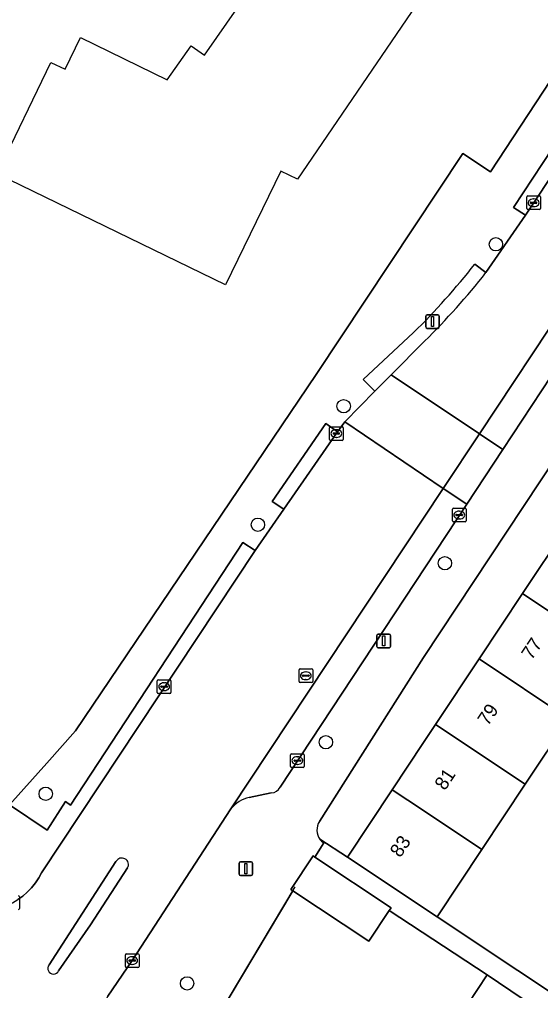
# Model space of a CAD drawing. Extents: x 159279 to 160377, y 384531 to 385888.
# Drawn here: x 159470.4 to 159508.6, y 385153.1 to 385224.2 of the extents above; entities that cross this region are included whole.
import ezdxf

# ---------------------------------------------------------------- set-up
doc = ezdxf.new("R2010")
doc.units = 0
for name, color, linetype in [('IMGEO_Boom', 7, 'Continuous'), ('IMGEO_Erf', 7, 'Continuous'), ('IMGEO_Groenvoorziening', 7, 'Continuous'), ('IMGEO_Hek', 7, 'Continuous'), ('IMGEO_Kolk', 7, 'Continuous'), ('IMGEO_Lichtmast', 7, 'Continuous'), ('IMGEO_Muur', 7, 'Continuous'), ('IMGEO_Pand', 7, 'Continuous'), ('IMGEO_Pand_nummerreeks', 7, 'Continuous'), ('IMGEO_Pand_vergunning_verleend', 7, 'Continuous'), ('IMGEO_Parkeervlak_open', 7, 'Continuous'), ('IMGEO_Rijbaan_lokaal_open', 7, 'Continuous'), ('IMGEO_Rioolput', 7, 'Continuous'), ('IMGEO_Verkeerseiland_gesloten', 7, 'Continuous'), ('IMGEO_Voetpad_open', 7, 'Continuous')]:
    doc.layers.add(name, color=color, linetype=linetype)

msp = doc.modelspace()

# ---------------------------------------------------------------- linework, layer by layer
at = {"layer": 'IMGEO_Boom'}
for centre in [(159505.303, 385207.734), (159494.152, 385195.876), (159487.871, 385187.199), (159501.57, 385184.377), (159492.848, 385171.268), (159472.328, 385167.492), (159482.683, 385153.611)]:
    msp.add_circle(centre, 0.489, dxfattribs=at)
at = {"layer": 'IMGEO_Erf'}
for points in [[(159530.535, 385223.584), (159500, 385177.475), (159492.38, 385165.468)], [(159492.402, 385164.162), (159494.421, 385162.858), (159497.704, 385167.792), (159500, 385171.242), (159500.889, 385172.578), (159504.075, 385177.365), (159507.261, 385182.153), (159510.446, 385186.939)], [(159510.641, 385172.99), (159507.456, 385168.204), (159504.27, 385163.417), (159500.989, 385158.486), (159512.815, 385150.618)], [(159518.635, 385141.802), (159516.069, 385143.517), (159513.503, 385145.232), (159510.937, 385146.948), (159508.371, 385148.663), (159505.805, 385150.378), (159503.239, 385152.093), (159504.664, 385154.224), (159497.479, 385158.937), (159495.985, 385156.692), (159490.429, 385160.388), (159484.85, 385151.066)]]:
    msp.add_lwpolyline(points, dxfattribs=at)
msp.add_arc((159493.374, 385164.832), 1.18, 147.37085, 214.5593, dxfattribs=at)
at = {"layer": 'IMGEO_Groenvoorziening'}
for points in [[(159546.86, 385274.842), (159546.212, 385275.888), (159529.172, 385250), (159504.899, 385213.047), (159502.888, 385214.394), (159492.142, 385198.211), (159474.504, 385172.106), (159472.407, 385169.747), (159469.674, 385166.696), (159472.443, 385164.841), (159473.77, 385166.921), (159474.152, 385166.668), (159486.771, 385185.901), (159487.681, 385185.313), (159489.779, 385188.336), (159488.914, 385188.908), (159492.841, 385194.619), (159493.711, 385194.005), (159494.162, 385194.645), (159494.243, 385194.728), (159496.427, 385196.975), (159495.586, 385197.832), (159499.271, 385201.267)], [(159503.765, 385206.282), (159504.576, 385205.661), (159507.461, 385209.864), (159506.582, 385210.436), (159511.549, 385217.953), (159512.448, 385217.36), (159515.225, 385221.522), (159514.344, 385222.135), (159519.542, 385230.066), (159520.431, 385229.512), (159522.635, 385232.842), (159521.758, 385233.406), (159534.923, 385253.438)], [(159436.757, 385236.409), (159430.587, 385217.007), (159435.719, 385206.014), (159438.506, 385200.578), (159441.573, 385195.295), (159443.21, 385192.716), (159445.93, 385188.732), (159465.252, 385165.282), (159467.724, 385165.189), (159469.674, 385166.696), (159472.407, 385169.747), (159474.504, 385172.106), (159492.142, 385198.211), (159502.888, 385214.394), (159504.899, 385213.047), (159529.172, 385250)]]:
    msp.add_lwpolyline(points, dxfattribs=at)
msp.add_arc((159460.86, 385240.209), 54.698, 314.60702, 321.6652, dxfattribs=at)
at = {"layer": 'IMGEO_Hek'}
msp.add_lwpolyline([(159529.172, 385250), (159504.899, 385213.047), (159502.888, 385214.394), (159492.142, 385198.211), (159474.504, 385172.106), (159472.407, 385169.747), (159469.674, 385166.696)], dxfattribs=at)
at = {"layer": 'IMGEO_Kolk'}
for p, q in [((159507.566, 385210.348), (159507.566, 385211.2)), ((159507.641, 385211.274), (159508.493, 385211.274)), ((159507.825, 385210.768), (159507.825, 385210.78)), ((159507.868, 385210.817), (159508.266, 385210.817)), ((159508.054, 385211.054), (159508.079, 385211.054)), ((159508.309, 385210.78), (159508.309, 385210.768)), ((159508.567, 385211.2), (159508.567, 385210.348)), ((159508.493, 385210.274), (159507.641, 385210.274)), ((159508.263, 385210.731), (159507.865, 385210.731)), ((159508.077, 385210.494), (159508.052, 385210.494)), ((159493.114, 385193.451), (159493.114, 385194.303)), ((159493.189, 385194.377), (159494.041, 385194.377)), ((159493.373, 385193.871), (159493.373, 385193.883)), ((159493.811, 385193.834), (159493.413, 385193.834)), ((159493.416, 385193.92), (159493.814, 385193.92)), ((159493.602, 385194.157), (159493.627, 385194.157)), ((159493.857, 385193.883), (159493.857, 385193.871)), ((159494.115, 385194.303), (159494.115, 385193.451)), ((159494.041, 385193.377), (159493.189, 385193.377)), ((159493.625, 385193.597), (159493.6, 385193.597)), ((159502.12, 385187.483), (159502.12, 385188.335)), ((159502.195, 385188.409), (159503.047, 385188.409)), ((159502.608, 385188.189), (159502.633, 385188.189)), ((159503.121, 385188.335), (159503.121, 385187.483)), ((159503.047, 385187.409), (159502.195, 385187.409)), ((159502.379, 385187.903), (159502.379, 385187.915)), ((159502.817, 385187.866), (159502.419, 385187.866)), ((159502.422, 385187.952), (159502.82, 385187.952)), ((159502.631, 385187.629), (159502.606, 385187.629)), ((159502.863, 385187.915), (159502.863, 385187.903)), ((159480.503, 385174.912), (159480.503, 385175.764)), ((159480.578, 385175.838), (159481.43, 385175.838)), ((159480.762, 385175.332), (159480.762, 385175.344)), ((159481.2, 385175.295), (159480.802, 385175.295)), ((159480.805, 385175.381), (159481.203, 385175.381)), ((159480.991, 385175.618), (159481.016, 385175.618)), ((159481.246, 385175.344), (159481.246, 385175.332)), ((159481.504, 385175.764), (159481.504, 385174.912)), ((159481.43, 385174.838), (159480.578, 385174.838)), ((159481.014, 385175.058), (159480.989, 385175.058)), ((159490.26, 385169.496), (159490.26, 385170.348)), ((159490.335, 385170.422), (159491.187, 385170.422)), ((159491.261, 385170.348), (159491.261, 385169.496)), ((159490.519, 385169.916), (159490.519, 385169.928)), ((159490.957, 385169.879), (159490.559, 385169.879)), ((159490.562, 385169.965), (159490.96, 385169.965)), ((159490.771, 385169.642), (159490.746, 385169.642)), ((159490.748, 385170.202), (159490.773, 385170.202)), ((159491.003, 385169.928), (159491.003, 385169.916)), ((159491.187, 385169.422), (159490.335, 385169.422)), ((159470.401, 385159.939), (159470.401, 385159.087)), ((159478.16, 385154.855), (159478.16, 385155.707)), ((159478.235, 385155.781), (159479.087, 385155.781)), ((159478.419, 385155.275), (159478.419, 385155.287)), ((159478.462, 385155.324), (159478.86, 385155.324)), ((159478.648, 385155.561), (159478.673, 385155.561)), ((159478.903, 385155.287), (159478.903, 385155.275)), ((159479.161, 385155.707), (159479.161, 385154.855)), ((159479.087, 385154.781), (159478.235, 385154.781)), ((159478.857, 385155.238), (159478.459, 385155.238)), ((159478.671, 385155.001), (159478.646, 385155.001))]:
    msp.add_line(p, q, dxfattribs=at)
for points in [[(159507.566, 385210.348), (159507.566, 385211.2)], [(159507.641, 385211.274), (159508.493, 385211.274)], [(159508.567, 385211.2), (159508.567, 385210.348)], [(159508.493, 385210.274), (159507.641, 385210.274)], [(159493.114, 385193.451), (159493.114, 385194.303)], [(159493.189, 385194.377), (159494.041, 385194.377)], [(159494.115, 385194.303), (159494.115, 385193.451)], [(159494.041, 385193.377), (159493.189, 385193.377)], [(159502.12, 385187.483), (159502.12, 385188.335)], [(159502.195, 385188.409), (159503.047, 385188.409)], [(159503.121, 385188.335), (159503.121, 385187.483)], [(159503.047, 385187.409), (159502.195, 385187.409)], [(159480.503, 385174.912), (159480.503, 385175.764)], [(159480.578, 385175.838), (159481.43, 385175.838)], [(159481.504, 385175.764), (159481.504, 385174.912)], [(159481.43, 385174.838), (159480.578, 385174.838)], [(159490.26, 385169.496), (159490.26, 385170.348)], [(159490.335, 385170.422), (159491.187, 385170.422)], [(159491.261, 385170.348), (159491.261, 385169.496)], [(159491.187, 385169.422), (159490.335, 385169.422)], [(159470.401, 385159.939), (159470.401, 385159.087)], [(159478.16, 385154.855), (159478.16, 385155.707)], [(159478.235, 385155.781), (159479.087, 385155.781)], [(159479.161, 385155.707), (159479.161, 385154.855)], [(159479.087, 385154.781), (159478.235, 385154.781)]]:
    msp.add_lwpolyline(points, dxfattribs=at)
for centre, radius, start, end in [((159507.643, 385211.198), 0.0765, 91.55205, 178.44795), ((159507.643, 385211.198), 0.0765, 91.55205, 178.44795), ((159507.865, 385210.777), 0.0403, 85.87752, 175.75265), ((159507.862, 385210.767), 0.0366, 178.93798, 274.71019), ((159508.266, 385210.774), 0.043, 264.86636, 352.45326), ((159508.27, 385210.779), 0.0386, 1.73085, 96.63898), ((159508.491, 385211.198), 0.0765, 1.55205, 88.44795), ((159508.491, 385211.198), 0.0765, 1.55205, 88.44795), ((159507.643, 385210.35), 0.0765, 181.55205, 268.44795), ((159507.643, 385210.35), 0.0765, 181.55205, 268.44795), ((159508.491, 385210.35), 0.0765, 271.55205, 358.44795), ((159508.491, 385210.35), 0.0765, 271.55205, 358.44795), ((159493.191, 385194.301), 0.0765, 91.55205, 178.44795), ((159493.191, 385194.301), 0.0765, 91.55205, 178.44795), ((159493.413, 385193.88), 0.0403, 85.87752, 175.75265), ((159493.41, 385193.87), 0.0366, 178.93798, 274.71019), ((159493.814, 385193.877), 0.043, 264.86636, 352.45326), ((159493.818, 385193.882), 0.0386, 1.73085, 96.63898), ((159494.039, 385194.301), 0.0765, 1.55205, 88.44795), ((159494.039, 385194.301), 0.0765, 1.55205, 88.44795), ((159493.191, 385193.453), 0.0765, 181.55205, 268.44795), ((159493.191, 385193.453), 0.0765, 181.55205, 268.44795), ((159494.039, 385193.453), 0.0765, 271.55205, 358.44795), ((159494.039, 385193.453), 0.0765, 271.55205, 358.44795), ((159502.197, 385188.333), 0.0765, 91.55205, 178.44795), ((159502.197, 385188.333), 0.0765, 91.55205, 178.44795), ((159503.045, 385188.333), 0.0765, 1.55205, 88.44795), ((159503.045, 385188.333), 0.0765, 1.55205, 88.44795), ((159502.197, 385187.485), 0.0765, 181.55205, 268.44795), ((159502.197, 385187.485), 0.0765, 181.55205, 268.44795), ((159502.419, 385187.912), 0.0403, 85.87752, 175.75265), ((159502.416, 385187.902), 0.0366, 178.93798, 274.71019), ((159502.82, 385187.909), 0.043, 264.86636, 352.45326), ((159502.824, 385187.914), 0.0386, 1.73085, 96.63898), ((159503.045, 385187.485), 0.0765, 271.55205, 358.44795), ((159503.045, 385187.485), 0.0765, 271.55205, 358.44795), ((159480.58, 385175.762), 0.0765, 91.55205, 178.44795), ((159480.58, 385175.762), 0.0765, 91.55205, 178.44795), ((159480.802, 385175.341), 0.0403, 85.87752, 175.75265), ((159480.799, 385175.331), 0.0366, 178.93798, 274.71019), ((159481.203, 385175.338), 0.043, 264.86636, 352.45326), ((159481.207, 385175.343), 0.0386, 1.73085, 96.63898), ((159481.428, 385175.762), 0.0765, 1.55205, 88.44795), ((159481.428, 385175.762), 0.0765, 1.55205, 88.44795), ((159480.58, 385174.914), 0.0765, 181.55205, 268.44795), ((159480.58, 385174.914), 0.0765, 181.55205, 268.44795), ((159481.428, 385174.914), 0.0765, 271.55205, 358.44795), ((159481.428, 385174.914), 0.0765, 271.55205, 358.44795), ((159490.337, 385170.346), 0.0765, 91.55205, 178.44795), ((159490.337, 385170.346), 0.0765, 91.55205, 178.44795), ((159491.185, 385170.346), 0.0765, 1.55205, 88.44795), ((159491.185, 385170.346), 0.0765, 1.55205, 88.44795), ((159490.559, 385169.925), 0.0403, 85.87752, 175.75265), ((159490.556, 385169.915), 0.0366, 178.93798, 274.71019), ((159490.96, 385169.922), 0.043, 264.86636, 352.45326), ((159490.964, 385169.927), 0.0386, 1.73085, 96.63898), ((159490.337, 385169.498), 0.0765, 181.55205, 268.44795), ((159490.337, 385169.498), 0.0765, 181.55205, 268.44795), ((159491.185, 385169.498), 0.0765, 271.55205, 358.44795), ((159491.185, 385169.498), 0.0765, 271.55205, 358.44795), ((159470.325, 385159.937), 0.0765, 1.55205, 88.44795), ((159470.325, 385159.937), 0.0765, 1.55205, 88.44795), ((159470.325, 385159.089), 0.0765, 271.55205, 358.44795), ((159470.325, 385159.089), 0.0765, 271.55205, 358.44795), ((159478.237, 385155.705), 0.0765, 91.55205, 178.44795), ((159478.237, 385155.705), 0.0765, 91.55205, 178.44795), ((159478.459, 385155.284), 0.0403, 85.87752, 175.75265), ((159478.864, 385155.286), 0.0386, 1.73085, 96.63898), ((159479.085, 385155.705), 0.0765, 1.55205, 88.44795), ((159479.085, 385155.705), 0.0765, 1.55205, 88.44795), ((159478.237, 385154.857), 0.0765, 181.55205, 268.44795), ((159478.237, 385154.857), 0.0765, 181.55205, 268.44795), ((159478.456, 385155.274), 0.0366, 178.93798, 274.71019), ((159478.86, 385155.281), 0.043, 264.86636, 352.45326), ((159479.085, 385154.857), 0.0765, 271.55205, 358.44795), ((159479.085, 385154.857), 0.0765, 271.55205, 358.44795)]:
    msp.add_arc(centre, radius, start, end, dxfattribs=at)
for centre, major_axis, ratio, start_param, end_param in [((159508.053, 385210.774), (-0.387, 0.002), 0.722429, 4.712389, 7.853982), ((159508.078, 385210.774), (-0.39, 0.002), 0.717154, 1.570796, 4.712389), ((159493.601, 385193.877), (-0.387, 0.002), 0.722429, 4.712389, 7.853982), ((159493.626, 385193.877), (-0.39, 0.002), 0.717154, 1.570796, 4.712389), ((159502.607, 385187.909), (-0.387, 0.002), 0.722429, 4.712389, 7.853982), ((159502.632, 385187.909), (-0.39, 0.002), 0.717154, 1.570796, 4.712389), ((159480.99, 385175.338), (-0.387, 0.002), 0.722429, 4.712389, 7.853982), ((159481.015, 385175.338), (-0.39, 0.002), 0.717154, 1.570796, 4.712389), ((159490.747, 385169.922), (-0.387, 0.002), 0.722429, 4.712389, 7.853982), ((159490.772, 385169.922), (-0.39, 0.002), 0.717154, 1.570796, 4.712389), ((159478.647, 385155.281), (-0.387, 0.002), 0.722429, 4.712389, 7.853982), ((159478.672, 385155.281), (-0.39, 0.002), 0.717154, 1.570796, 4.712389)]:
    msp.add_ellipse(centre, major_axis=major_axis, ratio=ratio, start_param=start_param, end_param=end_param, dxfattribs=at)
at = {"layer": 'IMGEO_Lichtmast'}
for p, q in [((159500.162, 385201.68), (159500.162, 385202.48)), ((159500.162, 385202.48), (159500.162, 385201.68)), ((159500.262, 385202.58), (159501.052, 385202.58)), ((159501.052, 385202.58), (159500.262, 385202.58)), ((159501.152, 385202.48), (159501.152, 385201.68)), ((159501.152, 385201.68), (159501.152, 385202.48)), ((159501.052, 385201.58), (159500.262, 385201.58)), ((159500.262, 385201.58), (159501.052, 385201.58)), ((159496.586, 385178.292), (159496.586, 385179.092)), ((159496.586, 385179.092), (159496.586, 385178.292)), ((159496.686, 385179.192), (159497.476, 385179.192)), ((159497.476, 385179.192), (159496.686, 385179.192)), ((159497.576, 385179.092), (159497.576, 385178.292)), ((159497.576, 385178.292), (159497.576, 385179.092)), ((159497.476, 385178.192), (159496.686, 385178.192)), ((159496.686, 385178.192), (159497.476, 385178.192)), ((159486.486, 385161.614), (159486.486, 385162.414)), ((159486.486, 385162.414), (159486.486, 385161.614)), ((159486.586, 385162.514), (159487.376, 385162.514)), ((159487.376, 385162.514), (159486.586, 385162.514)), ((159487.476, 385162.414), (159487.476, 385161.614)), ((159487.476, 385161.614), (159487.476, 385162.414)), ((159487.376, 385161.514), (159486.586, 385161.514)), ((159486.586, 385161.514), (159487.376, 385161.514))]:
    msp.add_line(p, q, dxfattribs=at)
for points in [[(159500.582, 385202.455), (159500.732, 385202.455), (159500.732, 385201.705), (159500.582, 385201.705), (159500.582, 385202.455)], [(159497.006, 385179.067), (159497.156, 385179.067), (159497.156, 385178.317), (159497.006, 385178.317), (159497.006, 385179.067)], [(159486.906, 385162.389), (159487.056, 385162.389), (159487.056, 385161.639), (159486.906, 385161.639), (159486.906, 385162.389)]]:
    msp.add_lwpolyline(points, dxfattribs=at)
for centre, start, end in [((159500.262, 385202.48), 90, 180), ((159500.262, 385202.48), 90, 180), ((159501.052, 385202.48), 0, 90), ((159501.052, 385202.48), 360, 90), ((159500.262, 385201.68), 180, 270), ((159500.262, 385201.68), 180, 270), ((159501.052, 385201.68), 270, 0), ((159501.052, 385201.68), 270, 0), ((159496.686, 385179.092), 90, 180), ((159496.686, 385179.092), 90, 180), ((159497.476, 385179.092), 0, 90), ((159497.476, 385179.092), 360, 90), ((159496.686, 385178.292), 180, 270), ((159496.686, 385178.292), 180, 270), ((159497.476, 385178.292), 270, 0), ((159497.476, 385178.292), 270, 0), ((159486.586, 385162.414), 90, 180), ((159486.586, 385162.414), 90, 180), ((159487.376, 385162.414), 0, 90), ((159487.376, 385162.414), 360, 90), ((159486.586, 385161.614), 180, 270), ((159486.586, 385161.614), 180, 270), ((159487.376, 385161.614), 270, 0), ((159487.376, 385161.614), 270, 0)]:
    msp.add_arc(centre, 0.1, start, end, dxfattribs=at)
at = {"layer": 'IMGEO_Muur'}
msp.add_lwpolyline([(159484.85, 385151.066), (159490.607, 385160.686)], dxfattribs=at)
at = {"layer": 'IMGEO_Pand'}
for points in [[(159517.013, 385182.564), (159510.446, 385186.939), (159507.261, 385182.153), (159513.827, 385177.778)], [(159513.827, 385177.778), (159507.261, 385182.153), (159504.075, 385177.365), (159510.641, 385172.99)], [(159510.641, 385172.99), (159504.075, 385177.365), (159500.889, 385172.578), (159507.456, 385168.204)], [(159507.456, 385168.204), (159500.889, 385172.578), (159500, 385171.242), (159497.704, 385167.792), (159500, 385166.262), (159504.27, 385163.417)], [(159500, 385159.144), (159500.989, 385158.486), (159504.27, 385163.417), (159500, 385166.262), (159497.704, 385167.792), (159494.421, 385162.858), (159498.583, 385160.087)], [(159492.047, 385162.863), (159491.928, 385162.942), (159490.291, 385160.48), (159490.429, 385160.388), (159495.985, 385156.692), (159497.479, 385158.937), (159497.623, 385159.154)], [(159503.239, 385152.093), (159505.805, 385150.378), (159507.23, 385152.509), (159504.664, 385154.224)]]:
    msp.add_lwpolyline(points, close=True, dxfattribs=at)
at = {"layer": 'IMGEO_Pand_vergunning_verleend'}
msp.add_lwpolyline([(159468.752, 385212.898), (159472.711, 385221.059), (159473.742, 385220.559), (159474.865, 385222.874), (159481.236, 385219.784), (159482.972, 385222.272), (159483.963, 385221.581), (159499.764, 385244.237), (159508.203, 385238.094), (159490.769, 385212.5), (159489.54, 385213.096), (159485.502, 385204.772)], close=True, dxfattribs=at)
at = {"layer": 'IMGEO_Parkeervlak_open'}
for points in [[(159523.226, 385222.717), (159504.103, 385193.86), (159505.818, 385192.716), (159513.601, 385204.527)], [(159489.511, 385167.971), (159503.167, 385188.694), (159501.449, 385189.855), (159485.898, 385166.387)], [(159487.223, 385167.226), (159488.849, 385167.561)]]:
    msp.add_lwpolyline(points, dxfattribs=at)
msp.add_lwpolyline([(159504.103, 385193.86), (159501.449, 385189.855), (159503.167, 385188.694), (159505.818, 385192.716)], close=True, dxfattribs=at)
for centre, radius, start, end in [((159488.812, 385168.361), 0.801, 272.68057, 330.86222), ((159487.759, 385164.914), 2.373, 103.04715, 141.63745)]:
    msp.add_arc(centre, radius, start, end, dxfattribs=at)
at = {"layer": 'IMGEO_Rijbaan_lokaal_open'}
for points in [[(159553.737, 385268.934), (159548.67, 385272.278), (159546.87, 385269.625), (159546.274, 385268.656), (159544.102, 385265.394), (159538.681, 385256.977), (159535.917, 385252.765), (159522.635, 385232.842), (159520.431, 385229.512), (159515.225, 385221.522), (159512.448, 385217.36), (159507.461, 385209.864), (159504.576, 385205.661)], [(159500.082, 385200.646), (159497.627, 385198.181), (159504.103, 385193.86), (159523.226, 385222.717), (159525.008, 385225.421), (159526.049, 385227.003), (159533.84, 385238.844), (159537.02, 385243.683), (159537.125, 385243.823), (159537.243, 385243.954), (159537.371, 385244.074), (159553.737, 385268.934)], [(159476.871, 385152.664), (159478.661, 385155.281), (159485.898, 385166.387), (159501.449, 385189.855), (159494.243, 385194.728), (159494.162, 385194.645), (159493.711, 385194.005), (159489.779, 385188.336), (159487.681, 385185.313), (159472.022, 385161.709), (159471.816, 385161.332), (159471.569, 385160.961), (159471.29, 385160.614), (159470.981, 385160.293), (159470.645, 385160.001), (159470.284, 385159.74)], [(159472.573, 385154.961), (159477.473, 385162.537)], [(159478.328, 385162.066), (159475.601, 385157.886), (159473.273, 385154.524)]]:
    msp.add_lwpolyline(points, dxfattribs=at)
msp.add_lwpolyline([(159496.427, 385196.975), (159494.243, 385194.728), (159501.449, 385189.855), (159504.103, 385193.86), (159497.627, 385198.181)], close=True, dxfattribs=at)
for centre, radius, start, end in [((159461.671, 385239.588), 54.698, 314.60702, 321.6652), ((159477.899, 385162.3), 0.488, 331.41352, 150.88775), ((159472.9, 385154.706), 0.415, 142.09072, 333.95739)]:
    msp.add_arc(centre, radius, start, end, dxfattribs=at)
at = {"layer": 'IMGEO_Rioolput'}
for p, q in [((159490.956, 385176.64), (159491.808, 385176.64)), ((159490.881, 385175.714), (159490.881, 385176.566)), ((159491.14, 385176.134), (159491.14, 385176.146)), ((159491.578, 385176.097), (159491.18, 385176.097)), ((159491.183, 385176.183), (159491.581, 385176.183)), ((159491.369, 385176.42), (159491.394, 385176.42)), ((159491.624, 385176.146), (159491.624, 385176.134)), ((159491.882, 385176.566), (159491.882, 385175.714)), ((159491.808, 385175.64), (159490.956, 385175.64)), ((159491.392, 385175.86), (159491.367, 385175.86))]:
    msp.add_line(p, q, dxfattribs=at)
for points in [[(159490.956, 385176.64), (159491.808, 385176.64)], [(159490.881, 385175.714), (159490.881, 385176.566)], [(159491.882, 385176.566), (159491.882, 385175.714)], [(159491.808, 385175.64), (159490.956, 385175.64)]]:
    msp.add_lwpolyline(points, dxfattribs=at)
for centre, radius, start, end in [((159490.958, 385176.564), 0.0765, 91.55205, 178.44795), ((159490.958, 385176.564), 0.0765, 91.55205, 178.44795), ((159491.806, 385176.564), 0.0765, 1.55205, 88.44795), ((159491.806, 385176.564), 0.0765, 1.55205, 88.44795), ((159491.18, 385176.143), 0.0403, 85.87752, 175.75265), ((159491.177, 385176.133), 0.0366, 178.93798, 274.71019), ((159491.581, 385176.14), 0.043, 264.86636, 352.45326), ((159491.585, 385176.145), 0.0386, 1.73085, 96.63898), ((159490.958, 385175.716), 0.0765, 181.55205, 268.44795), ((159490.958, 385175.716), 0.0765, 181.55205, 268.44795), ((159491.806, 385175.716), 0.0765, 271.55205, 358.44795), ((159491.806, 385175.716), 0.0765, 271.55205, 358.44795)]:
    msp.add_arc(centre, radius, start, end, dxfattribs=at)
for centre, major_axis, ratio, start_param, end_param in [((159491.368, 385176.14), (-0.387, 0.002), 0.722429, 4.712389, 7.853982), ((159491.393, 385176.14), (-0.39, 0.002), 0.717154, 1.570796, 4.712389)]:
    msp.add_ellipse(centre, major_axis=major_axis, ratio=ratio, start_param=start_param, end_param=end_param, dxfattribs=at)
at = {"layer": 'IMGEO_Verkeerseiland_gesloten'}
for points in [[(159477.473, 385162.537), (159472.573, 385154.961)], [(159473.273, 385154.524), (159475.601, 385157.886), (159478.328, 385162.066)]]:
    msp.add_lwpolyline(points, dxfattribs=at)
for centre, radius, start, end in [((159477.899, 385162.3), 0.488, 331.41352, 150.88775), ((159472.9, 385154.706), 0.415, 142.09072, 333.95739)]:
    msp.add_arc(centre, radius, start, end, dxfattribs=at)
at = {"layer": 'IMGEO_Voetpad_open'}
for points in [[(159492.38, 385165.468), (159500, 385177.475), (159530.535, 385223.584)], [(159504.576, 385205.661), (159503.765, 385206.282)], [(159513.601, 385204.527), (159505.818, 385192.716), (159503.167, 385188.694), (159489.511, 385167.971)], [(159499.271, 385201.267), (159495.586, 385197.832), (159496.427, 385196.975), (159497.627, 385198.181), (159500.082, 385200.646)], [(159488.849, 385167.561), (159487.223, 385167.226)], [(159485.898, 385166.387), (159478.661, 385155.281), (159476.871, 385152.664), (159476.343, 385151.693), (159475.903, 385150.678), (159475.575, 385149.685), (159479.774, 385144.498), (159481.749, 385146.078), (159482.541, 385145.088), (159485.574, 385147.627)], [(159484.85, 385151.066), (159490.429, 385160.388), (159490.291, 385160.48), (159491.928, 385162.942), (159492.047, 385162.863), (159492.693, 385163.902), (159492.518, 385164.02)], [(159492.518, 385164.02), (159492.693, 385163.902), (159492.047, 385162.863), (159497.623, 385159.154), (159497.479, 385158.937), (159504.664, 385154.224), (159507.23, 385152.509), (159509.796, 385150.794)], [(159512.815, 385150.618), (159500.989, 385158.486), (159500, 385159.144), (159498.583, 385160.087), (159494.421, 385162.858), (159492.402, 385164.162)]]:
    msp.add_lwpolyline(points, dxfattribs=at)
for points in [[(159512.448, 385217.36), (159511.549, 385217.953), (159506.582, 385210.436), (159507.461, 385209.864)], [(159489.779, 385188.336), (159493.711, 385194.005), (159492.841, 385194.619), (159488.914, 385188.908)], [(159469.674, 385166.696), (159465.087, 385162.769), (159463.476, 385162.36), (159462.87, 385162.603), (159463.892, 385161.413), (159465.043, 385160.072), (159468.531, 385158.824), (159469.901, 385159.512), (159470.284, 385159.74), (159470.645, 385160.001), (159470.981, 385160.293), (159471.29, 385160.614), (159471.569, 385160.961), (159471.816, 385161.332), (159472.022, 385161.709), (159487.681, 385185.313), (159486.771, 385185.901), (159474.152, 385166.668), (159473.77, 385166.921), (159472.443, 385164.841)]]:
    msp.add_lwpolyline(points, close=True, dxfattribs=at)
for centre, radius, start, end in [((159460.86, 385240.209), 54.698, 314.60702, 321.6652), ((159461.671, 385239.588), 54.698, 314.60702, 321.6652), ((159488.812, 385168.361), 0.801, 272.68057, 330.86222), ((159487.759, 385164.914), 2.373, 103.04715, 141.63745), ((159493.374, 385164.832), 1.18, 147.37085, 214.5593), ((159493.366, 385164.831), 1.173, 214.76216, 223.72871), ((159493.366, 385164.831), 1.173, 214.76216, 223.72871)]:
    msp.add_arc(centre, radius, start, end, dxfattribs=at)

# ---------------------------------------------------------------- texts
at = {"layer": 'IMGEO_Pand_nummerreeks'}
for s, p in [('77', (159507.928, 385177.233)), ('79', (159504.718, 385172.41)), ('81', (159501.571, 385167.681)), ('83', (159498.299, 385162.764))]:
    msp.add_text(s, height=1, rotation=56.35613, dxfattribs=at).set_placement(p)

doc.saveas('drawing.dxf')
